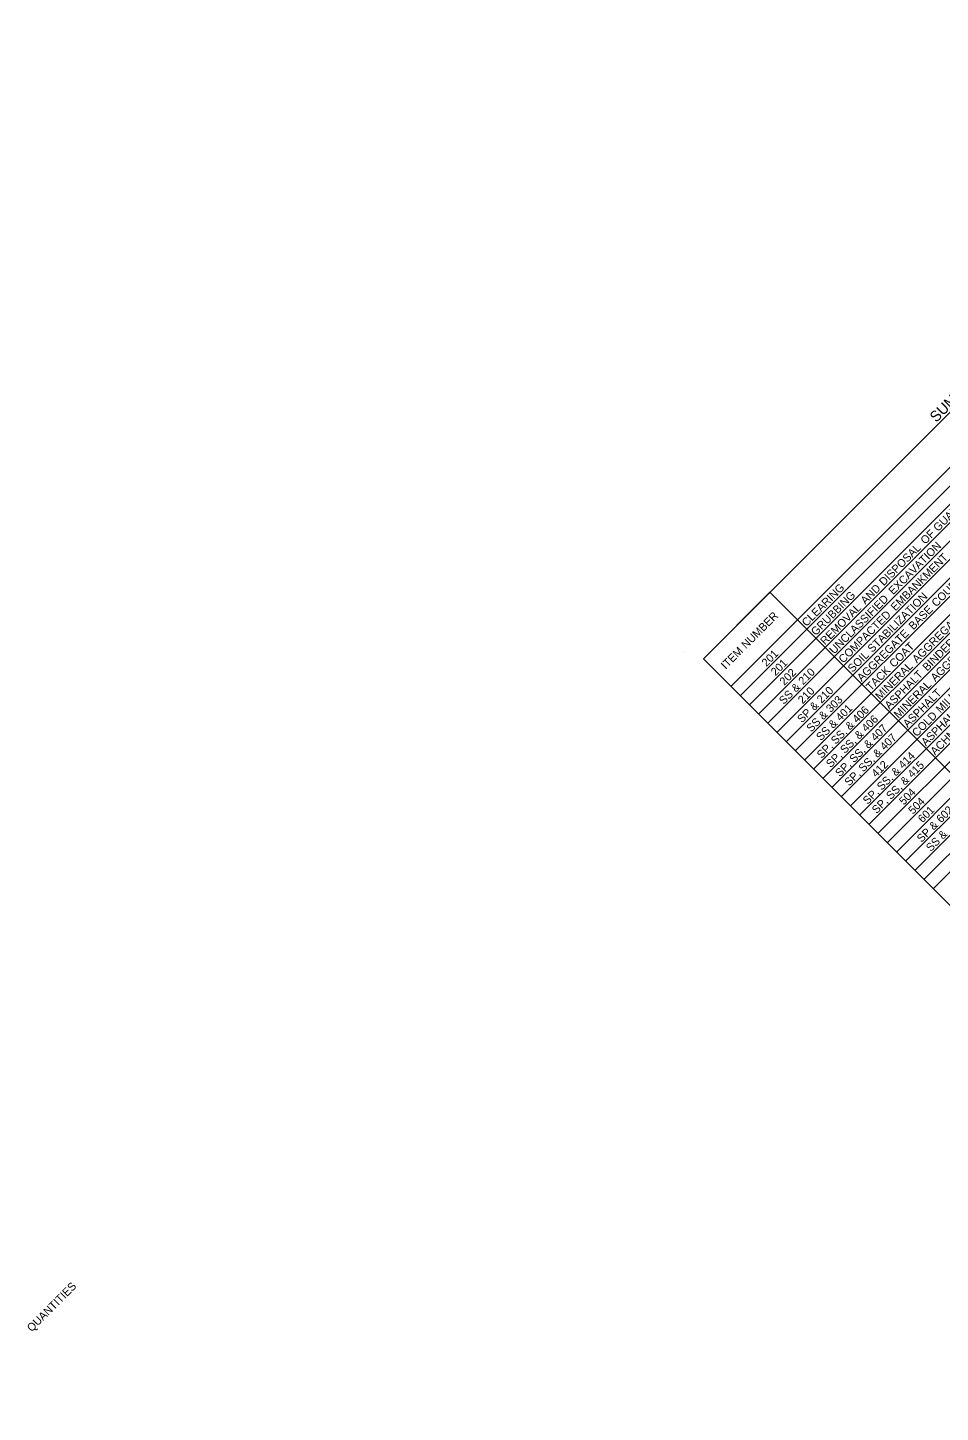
# Model space of a CAD drawing. Extents: x 1675667 to 1681231, y 227227 to 232694.
# Drawn here: x 1679194 to 1679879, y 231280 to 232318 of the extents above; entities that cross this region are included whole.
import ezdxf

# ---------------------------------------------------------------- set-up
doc = ezdxf.new("R2010")
doc.units = 0
doc.layers.add('Default', color=7, linetype='Continuous')
doc.layers.add('R_Border', color=7, linetype='Continuous')

msp = doc.modelspace()

# ---------------------------------------------------------------- linework, layer by layer
at = {"layer": 'Default'}
for p, q in [((1679701.2, 231845), (1680174.4, 232318.3)), ((1679721.9, 231824.3), (1680195.1, 232297.6)), ((1679728.8, 231817.4), (1680202, 232290.7)), ((1679735.7, 231810.5), (1680208.9, 232283.9)), ((1679742.6, 231803.6), (1680215.8, 232277)), ((1679749.5, 231796.7), (1680222.7, 232270.1)), ((1679756.4, 231789.8), (1680229.6, 232263.2)), ((1679763.3, 231782.9), (1680236.5, 232256.3)), ((1679770.2, 231776), (1680243.4, 232249.4)), ((1679777.1, 231769.1), (1680250.3, 232242.5)), ((1679783.9, 231762.2), (1680257.2, 232235.6)), ((1679790.8, 231755.4), (1680264.1, 232228.7)), ((1679797.7, 231748.5), (1680271, 232221.8)), ((1679804.6, 231741.6), (1680277.9, 232214.9)), ((1679811.5, 231734.7), (1680284.8, 232208)), ((1679818.4, 231727.8), (1680291.7, 232201.1)), ((1679825.3, 231720.9), (1680298.6, 232194.2)), ((1679832.2, 231714), (1680305.5, 232187.3)), ((1679839.1, 231707.1), (1680312.3, 232180.5)), ((1679846, 231700.2), (1680319.2, 232173.6)), ((1679852.9, 231693.3), (1680326.1, 232166.7)), ((1679859.8, 231686.4), (1680333, 232159.8)), ((1679866.7, 231679.5), (1680339.9, 232152.9)), ((1679873.6, 231672.6), (1680346.8, 232146)), ((1679701.2, 231845), (1679751.2, 231895)), ((1680192.1, 231454.1), (1679751.2, 231895)), ((1680192.1, 231454.1), (1679771.9, 231874.3)), ((1679687.4, 231850.5), (1679687.4, 231850.5)), ((1680266.3, 231280.1), (1679701.2, 231845)), ((1680266.3, 231280.1), (1679701.2, 231845))]:
    msp.add_line(p, q, dxfattribs=at)

# ---------------------------------------------------------------- texts
for s, height, p in [(' SUMMARY', 8, (1679873.8, 232019.8)), (' GUARDRAIL', 6, (1679875.7, 231938.5)), (' OF', 6, (1679866.1, 231928.9)), (' DISPOSAL', 6, (1679835, 231897.8)), (' EXCAVATION', 6, (1679842.1, 231891.1)), (' EMBANKMENT', 6, (1679843.7, 231878.9)), (' COURSE', 6, (1679874.4, 231882)), ('CLEARING', 6, (1679778.6, 231868.9)), (' AND', 6, (1679821.2, 231883.9)), ('GRUBBING', 6, (1679785.5, 231862)), ('UNCLASSIFIED', 6, (1679799.3, 231848.2)), (' STABILIZATION', 6, (1679826.4, 231847.8)), (' NUMBER', 6, (1679731.7, 231850.6)), ('REMOVAL', 6, (1679792.4, 231855.1)), ('COMPACTED', 6, (1679806.2, 231841.4)), (' BASE', 6, (1679857.2, 231864.8)), (' AGGREGATE', 6, (1679859.9, 231839.9)), ('AGGREGATE', 6, (1679820, 231827.6)), (' AGGREGATE', 6, (1679873.7, 231826.1)), (' COAT', 6, (1679842.7, 231836.5)), (' BINDER', 6, (1679867.6, 231833.8)), ('ITEM', 6, (1679718, 231836.8)), ('201', 6, (1679748.5, 231838.8)), ('SOIL', 6, (1679813.1, 231834.5)), ('201', 6, (1679755.4, 231831.9)), ('202', 6, (1679761.9, 231824.7)), (' 210', 6, (1679774.5, 231823.5)), ('TACK', 6, (1679826.9, 231820.7)), ('MINERAL', 6, (1679833.8, 231813.8)), ('ASPHALT', 6, (1679840.7, 231806.9)), (' &', 6, (1679769.1, 231818)), ('MINERAL', 6, (1679847.6, 231800)), (' MILLING', 6, (1679877.5, 231802.4)), ('SS', 6, (1679761.5, 231810.4)), ('210', 6, (1679775.7, 231810.9)), (' 210', 6, (1679788.3, 231809.7)), (' 303', 6, (1679795.2, 231802.8)), ('ASPHALT', 6, (1679854.5, 231793.1)), ('SP', 6, (1679775.2, 231796.6)), (' &', 6, (1679782.9, 231804.2)), (' &', 6, (1679789.7, 231797.3)), (' 401', 6, (1679802.5, 231796.3)), (' 406', 6, (1679815, 231795)), ('COLD', 6, (1679861.3, 231786.2)), ('ASPHALT', 6, (1679868.2, 231779.3)), ('SS', 6, (1679782.1, 231789.7)), ('SS', 6, (1679789.4, 231783.2)), (' &', 6, (1679797, 231790.8)), (' &', 6, (1679809.6, 231789.6)), (' 406', 6, (1679821.9, 231788.2)), (' 407', 6, (1679828.8, 231781.3)), (' SS,', 6, (1679798.9, 231778.9)), (' SS,', 6, (1679805.8, 231772)), (' &', 6, (1679816.5, 231782.7)), (' &', 6, (1679823.4, 231775.8)), (' 407', 6, (1679835.7, 231774.4)), ('ACHM', 6, (1679875.1, 231772.4)), ('SP,', 6, (1679789.9, 231769.9)), ('SP,', 6, (1679796.8, 231763)), (' SS,', 6, (1679812.7, 231765.1)), (' &', 6, (1679830.3, 231768.9)), (' 414', 6, (1679849.5, 231760.6)), ('SP,', 6, (1679803.7, 231756.1)), (' SS,', 6, (1679819.6, 231758.2)), ('412', 6, (1679830.9, 231755.7)), (' &', 6, (1679844.1, 231755.1)), (' 415', 6, (1679856.4, 231753.7)), ('SP,', 6, (1679810.6, 231749.2)), (' SS,', 6, (1679833.4, 231744.4)), (' &', 6, (1679850.9, 231748.2)), ('SP,', 6, (1679824.4, 231735.4)), (' SS,', 6, (1679840.3, 231737.5)), ('504', 6, (1679851.6, 231735)), ('SP,', 6, (1679831.2, 231728.5)), ('504', 6, (1679858.5, 231728.1)), ('601', 6, (1679865.7, 231721.7)), (' 602', 6, (1679878, 231720.1)), (' &', 6, (1679872.5, 231714.6)), ('SP', 6, (1679864.9, 231707)), ('SS', 6, (1679871.8, 231700.1)), (' &', 6, (1679879.4, 231707.7))]:
    msp.add_text(s, height=height, rotation=45.007, dxfattribs=at).set_placement(p)
at = {"layer": 'R_Border'}
msp.add_text('QUANTITIES', height=6, rotation=45.007, dxfattribs=at).set_placement((1679197.3, 231340))

doc.saveas('drawing.dxf')
